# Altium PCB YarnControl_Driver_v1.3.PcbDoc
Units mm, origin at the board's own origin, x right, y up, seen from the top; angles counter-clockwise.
Board outline 80 x 60 mm, 2 copper layers (Top Layer, Bottom Layer); 141 components, 102 nets, 453 pads, 202 vias.
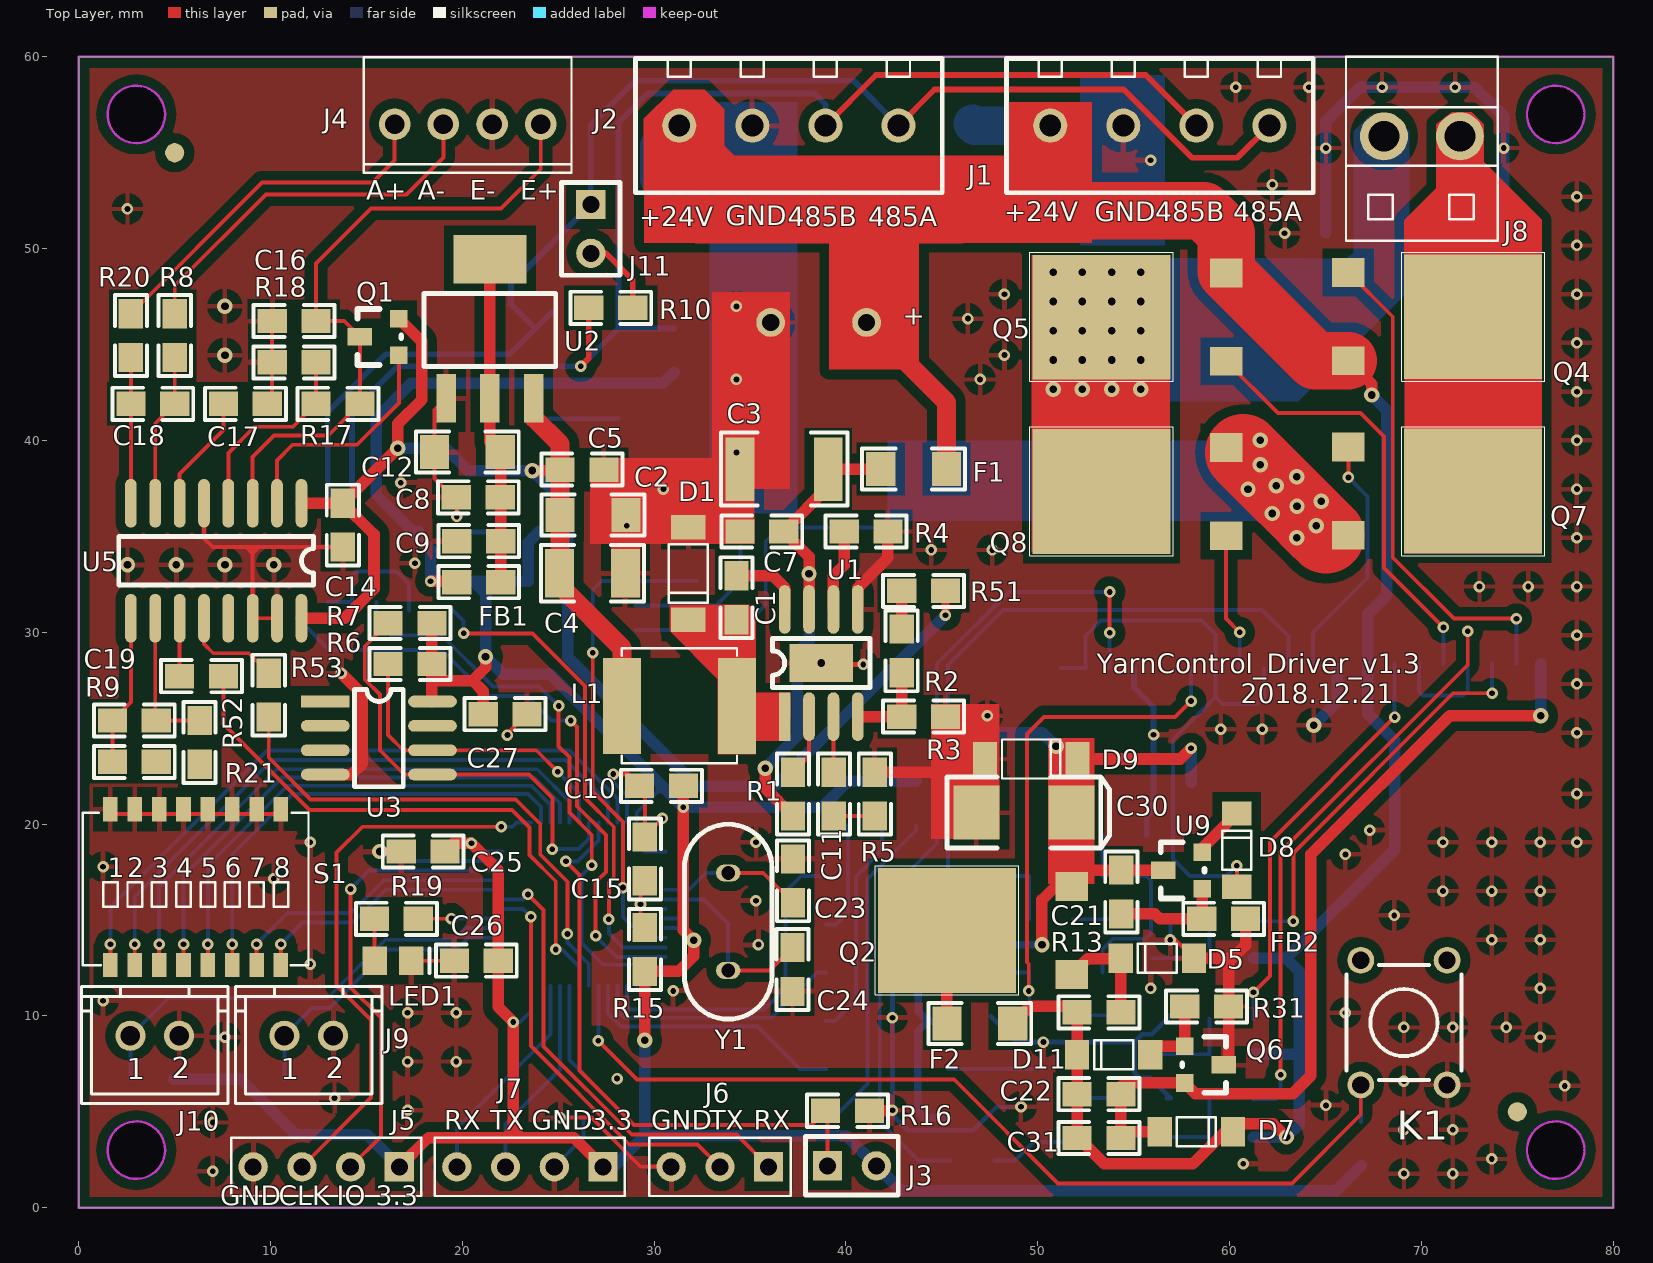
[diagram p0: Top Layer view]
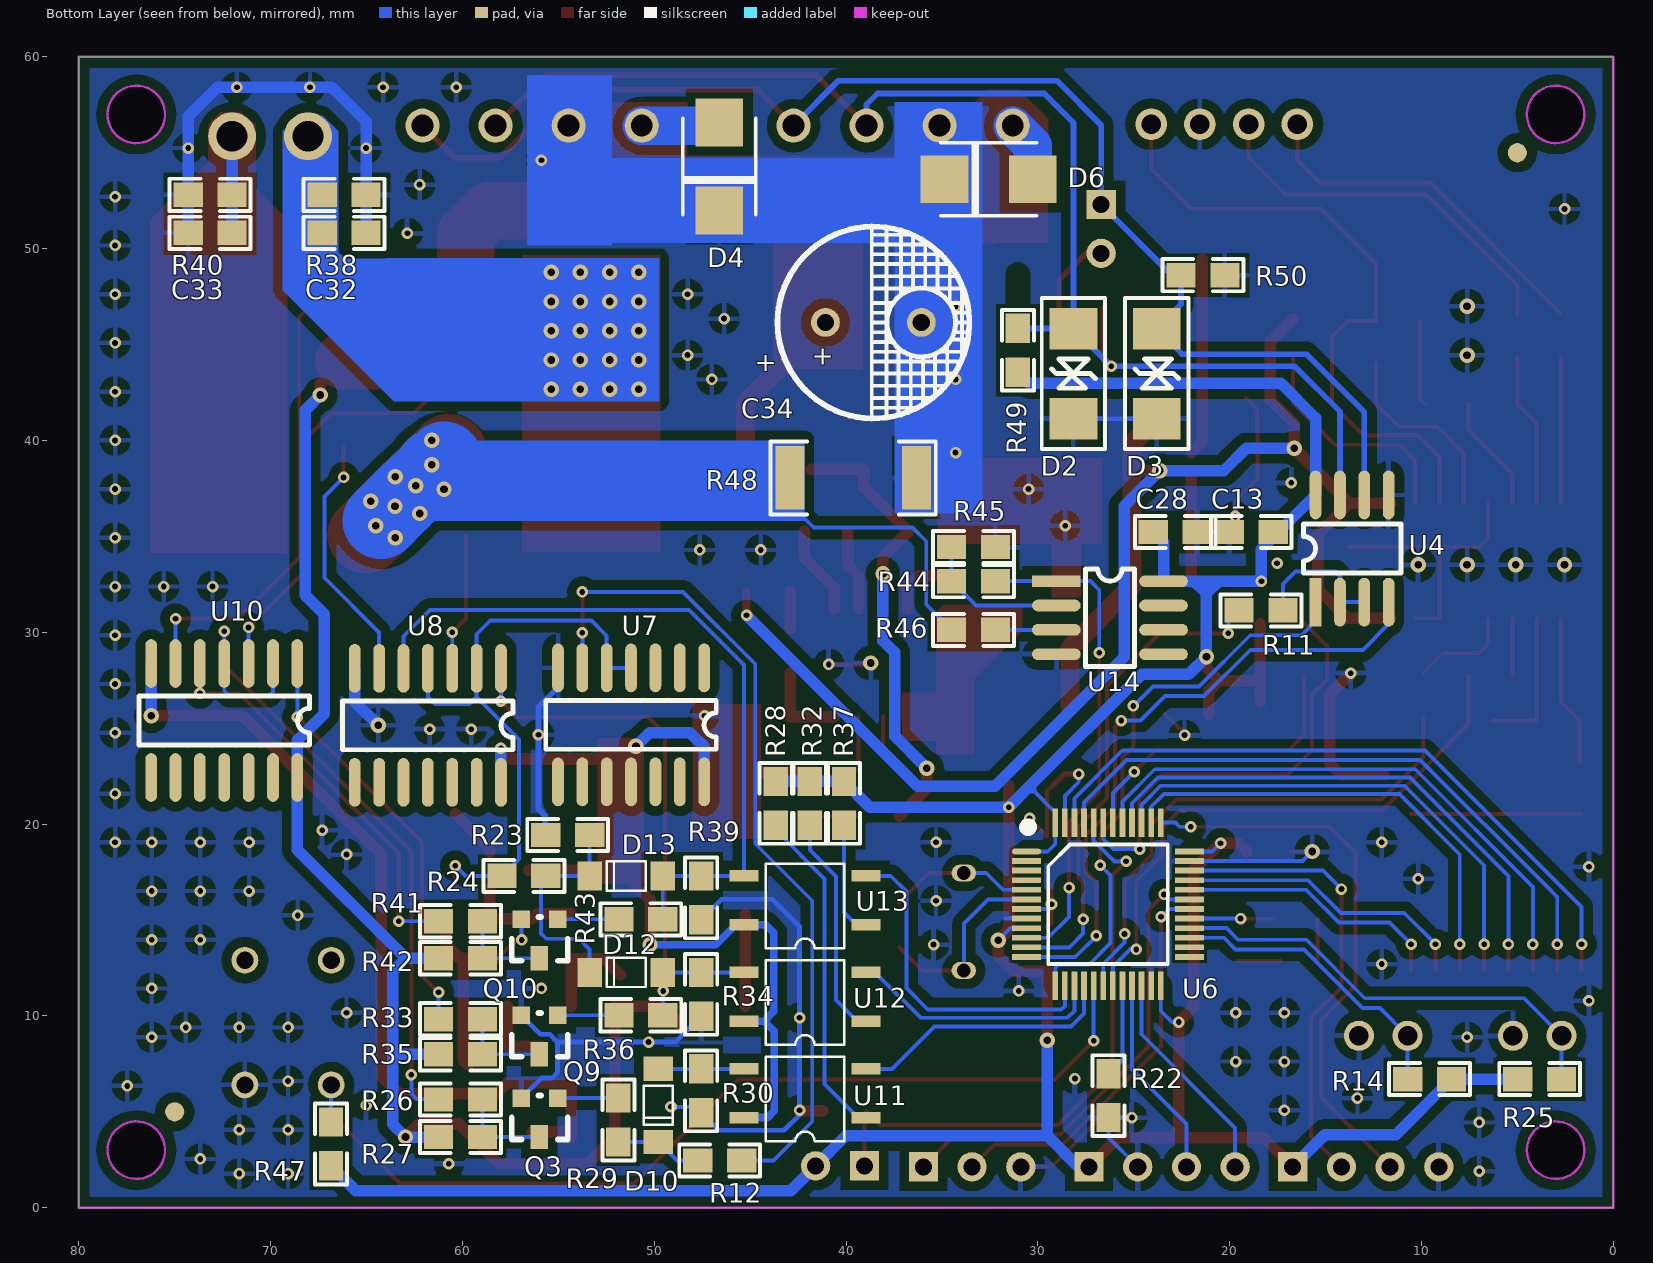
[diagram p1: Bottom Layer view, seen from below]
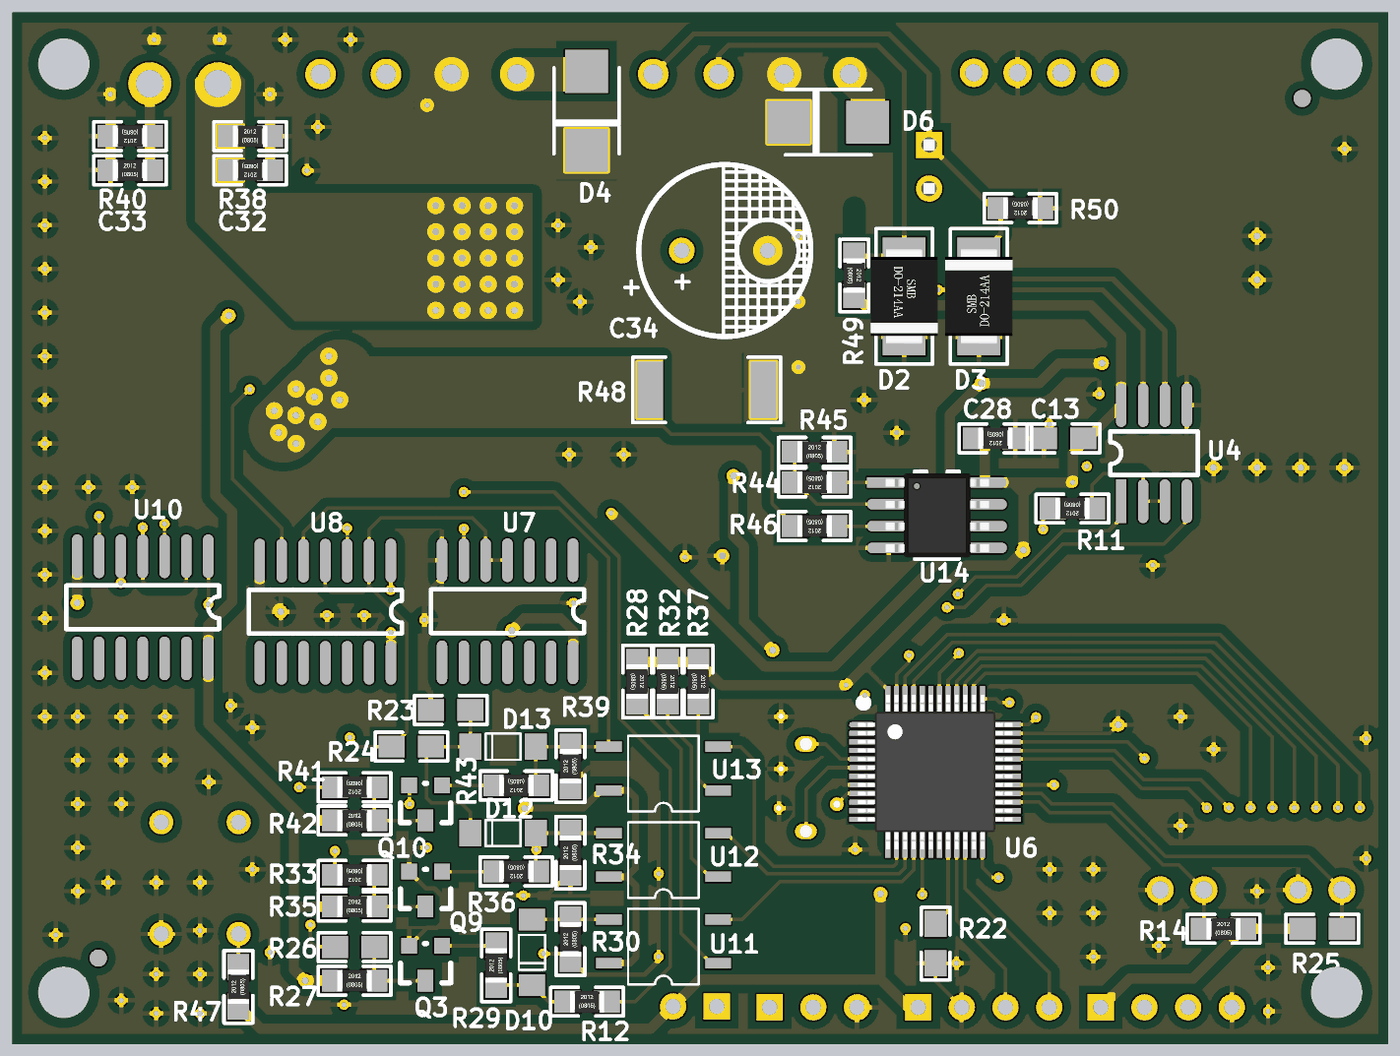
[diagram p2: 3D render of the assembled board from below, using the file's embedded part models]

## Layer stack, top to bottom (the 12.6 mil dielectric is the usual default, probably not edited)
Top Layer: signal copper 0.0356
Dielectric: dielectric 0.32, FR-4, Dk 4.8
Bottom Layer: signal copper 0.0356

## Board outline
0,0 80,0 80,60 0,60
cut-out: 3,1.5 cw(c3,3) 1.5,3 cw(c3,3) 3,4.5 cw(c3,3) 4.5,3 cw(c3,3)
cut-out: 75.5,3 ccw(c77,3) 77,1.5 ccw(c77,3) 78.5,3 ccw(c77,3) 77,4.5 ccw(c77,3)
cut-out: 75.5,57 ccw(c77,57) 77,55.5 ccw(c77,57) 78.5,57 ccw(c77,57) 77,58.5 ccw(c77,57)
cut-out: 3,55.5 cw(c3,57) 1.5,57 cw(c3,57) 3,58.5 cw(c3,57) 4.5,57 cw(c3,57)

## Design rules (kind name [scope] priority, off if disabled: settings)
Clearance LQFP_48 [(HasFootprint('LQFP_48'))] p1: gap=0.178
Clearance poly [inpoly] p2: gap=0.508
Clearance [All] p3: gap=0.203
Height [All] p1: minheight=0 maxheight=50 prefheight=12.7
HoleSize [All] p1: absolutevalues=TRUE maxlimit=4 minlimit=0.025 maxpercent=80.000 minpercent=20.000
MinimumSolderMaskSliver [All] p1: minsoldermaskwidth=0
PolygonConnect [All] p1: connectstyle=Relief reliefconductorwidth=0.254 reliefentries=4 polygonreliefangle="90 Angle"
RoutingVias [All] p1: holewidth=0.711 width=1.27 viastyle="Through Hole" minholewidth=0.3 minwidth=0.6 maxholewidth=0.711 maxwidth=1.27
SilkToSilkClearance [All] p1: silktosilkclearance=0
SilkscreenOverComponentPads [All] p1: minsilkscreentomaskgap=0
SolderMaskExpansion [All] p1: expansion=0.102
Width [All] p1: maxlimit=5 minlimit=0.203 preferedwidth=0.203
23 further rules are at their usual default settings.

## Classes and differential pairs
component class YarnControl_Driver_v1.3: C1 C2 C3 C4 C5 C7 C8 C9 C10 C11 C12 C13 C14 C15 C16 C17 C18 C19 C23 C24 C25 C26 C27 C28 D1 D2 D3 F1 FB1 J1 J2 J3 J4 J5 J6 J7 J9 J10 J11 K1 L1 LED1 Q1 R1 R2 R3 R4 R5 R6 R7 R8 R9 R10 R11 R14 R15 R16 R17 R18 R19 R20 R21 R22 R25 R47 R49 R50 R51 R52 R53 R? S1 U1 U2 U3 U4 U5 U6 Y1
component class YarnControl_motor_v1.3: C21 C22 C30 C31 C32 C33 C34 D4 D5 D6 D7 D8 D9 D10 D11 D12 D13 F2 FB2 J8 Q2 Q3 Q4 Q5 Q6 Q7 Q8 Q9 Q10 R12 R13 R23 R24 R26 R27 R28 R29 R30 R31 R32 R33 R34 R35 R36 R37 R38 R39 R40 R41 R42 R43 R44 R45 R46 R48 U7 U8 U9 U10 U11 U12 U13 U14

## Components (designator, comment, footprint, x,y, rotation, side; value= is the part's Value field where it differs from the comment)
C1 "0.1uF" 0805#1 34.29,32.944 r270 top
C2 "22uF" 1206 28.524,36.119 r180 top
C3 "47uF" 1812 36.779,38.506 r180 top
C4 "47uF" 1210 28.499,33.071 r180 top
C5 "0.1uF" 0805#1 27.381,38.481 r180 top
C7 "0.1uF" 0805#1 36.754,35.255 r180 top
C8 "10uF" 0805#1 19.685,37.033 r0 top
C9 "0.1uF" 0805#1 19.71,34.747 r0 top
C10 "0.1uF" 0805#2 30.378,21.996 r180 top
C11 "150pF" 0805#1 39.37,22.708 r270 top
C12 "22uF" 1206 21.971,39.395 r180 top
C13 "0.1uF" 0805#1 20.015,35.23 r180 bottom
C14 "1uF" 0805#1 13.767,34.442 r90 top
C15 "0.1uF" 0805#1 29.515,19.329 r270 top
C16 "1uF" 0805#1 10.084,46.228 r0 top
C17 "1uF" 0805#1 7.544,41.91 r0 top
C18 "0.1uF" 0805#1 5.004,41.91 r180 top
C19 "0.1uF" 0805#1 1.753,25.4 r0 top
C21 "10uF" 0805#1 54.356,17.602 r270 top
C22 "10nF" 0805#1 52.045,5.918 r0 top
C23 "22pF" 0805#2 37.236,17.043 r270 top
C24 "22pF" 0805#2 37.211,12.421 r90 top
C25 "0.1uF" 0805#2 17.958,18.567 r0 top
C26 "0.1uF" 0805#2 20.726,12.878 r0 top
C27 "0.1uF" 0805#2 22.225,25.73 r180 top
C28 "0.1uF" 0805#2 22.835,35.23 r0 bottom
C30 "100uF" CA6032-C 49.276,20.599 r0 top
C31 "22uF" 0805#2 53.188,3.632 r180 top
C32 "10nF" 0805#2 66.167,50.825 r0 bottom
C33 "10nF" 0805#2 73.152,50.825 r180 bottom
C34 "1000uF/35V" CAP-5MM 41.072,46.152 r180 bottom
D1 "1N5819" Diode_TP2 31.775,35.484 r270 top
D2 "SMBJ6.5CA" SMBJ_DO-214 28.143,43.485 r270 bottom
D3 "SMBJ6.5CA" SMBJ_DO-214 23.8,43.485 r90 bottom
D4 "SMCJ24A" DO-214AA/SMB 46.609,54.28 r270 bottom
D5 "ZMM6V2" DIDODE_LL-34 56.236,13.005 r180 top
D6 "SMCJ24A" DO-214AA/SMB 32.563,53.619 r0 bottom
D7 "ZMM6V2" DIDODE_LL-34 58.268,3.962 r0 top
D8 "1N4148" DIDODE_LL-34 60.376,18.644 r90 top
D9 "SMAJ5.0A" Diode_TP2 47.244,23.393 r0 top
D10 "1N4148" DIDODE_LL-34 49.784,5.334 r270 bottom
D11 "ZMM6V2" DIDODE_LL-34 53.95,7.976 r180 top
D12 "1N4148" DIDODE_LL-34 51.46,12.268 r0 bottom
D13 "1N4148" DIDODE_LL-34 51.46,17.297 r0 bottom
F1 "FUSE" 1206 45.237,38.506 r180 top
F2 "FUSE" 1206 45.263,9.601 r0 top
FB1 "FERRITE" 0805#1 21.996,32.614 r180 top
FB2 "FERRITE" 0805#2 59.69,15.062 r0 top
J1 "SH-4" J381-180 56.363,56.413 r180 top
J2 "SH-4" J381-180 37.02,56.413 r180 top
J3 "Jumper" J254-2 39.04,2.184 r0 top
J4 "SH-4" KF2510-4 24.088,56.49 r180 top
J5 "SH-4" J254-4 16.713,2.134 r180 top
J6 "SH-3" J2.54-3 33.426,2.134 r180 top
J7 "SH-4" J254-4 27.33,2.134 r180 top
J8 "SH-2" CH3.96-2P 70.028,55.855 r0 top
J9 "SWITCH1" XH2.54-2T 10.719,8.966 r0 top
J10 "SWITCH2" XH2.54-2T 2.692,8.966 r0 top
J11 "Jumper" J254-2 26.695,52.299 r270 top
K1 "BUTTON_4" Button1 69.088,9.652 r90 top
L1 "4.7uH" Inductance6*6 31.318,26.162 r180 top
LED1 "GREEN" LED 16.383,12.878 r0 top
Q1 "S8550" 901X_SOT-23 14.656,45.415 r90 top
Q2 "2SD1760" TO-252-2L 48.514,14.453 r90 top
Q3 "MMBT3904" SOT-23 55.982,3.683 r0 bottom
Q4 "NCE40P70K" TO-252 72.695,46.457 r270 top
Q5 "NCE40P70K" TO-252 53.315,46.431 r90 top
Q6 "MMBT2907A" 901X_SOT-23 59.69,7.442 r270 top
Q7 "NCE6075" TO-252 72.695,37.363 r270 top
Q8 "NCE6075" TO-252 53.315,37.338 r90 top
Q9 "MMBT3904" SOT-23 55.982,8.001 r0 bottom
Q10 "MMBT3904" SOT-23 55.982,13.005 r0 bottom
R1 "100K" 0805#1 37.236,22.708 r270 top
R2 "200K" 0805#1 42.901,30.175 r270 top
R3 "40.2K" 0805#1 45.187,25.603 r180 top
R4 "100K" 0805#1 42.189,35.255 r180 top
R5 "100K" 0805#1 41.504,22.708 r270 top
R6 "10K" 0805#1 16.129,28.346 r0 top
R7 "10K" 0805#1 16.129,30.48 r0 top
R8 "1K" 0805#2 5.004,45.466 r90 top
R9 "1K" 0805#2 2.896,23.241 r0 top
R10 "120R" 0805#1 26.594,46.914 r0 top
R11 "1K" 0805#2 18.364,31.14 r0 bottom
R12 "4.7K" 0805#2 46.584,2.464 r180 bottom
R13 "5.6K" 0805#2 53.188,10.185 r0 top
R14 "10K" 0805#2 9.576,6.706 r180 bottom
R15 "10K" 0805#1 29.515,14.605 r270 top
R16 "10K" 0805#1 38.938,5.055 r0 top
R17 "20K" 0805#1 12.37,41.91 r0 top
R18 "8.2K" 0805#1 12.37,44.069 r180 top
R19 "1K" 0805#1 15.418,15.062 r0 top
R20 "1K" 0805#1 2.718,44.323 r90 top
R21 "1K" 0805#1 6.299,25.4 r270 top
R22 "10K" 0805#1 26.314,4.699 r90 bottom
R23 "10K" 0805#1 55.651,19.431 r180 bottom
R24 "10K" 0805#1 55.651,17.297 r0 bottom
R25 "10K" 0805#1 4.978,6.706 r180 bottom
R26 "10K" 0805#1 58.953,5.639 r0 bottom
R27 "10K" 0805#2 60.096,3.683 r180 bottom
R28 "510R" 0805#2 43.663,21.082 r270 bottom
R29 "10K" 0805#2 51.867,4.572 r90 bottom
R30 "510R" 0805#2 47.549,6.096 r90 bottom
R31 "5.6K" 0805#2 58.801,10.49 r180 top
R32 "510R" 0805#2 41.885,21.082 r270 bottom
R33 "10K" 0805#2 60.096,9.83 r0 bottom
R34 "4.7K" 0805#2 47.549,11.125 r90 bottom
R35 "10K" 0805#2 60.096,8.001 r180 bottom
R36 "10K" 0805#2 50.698,10.033 r0 bottom
R37 "510R" 0805#2 40.107,21.082 r270 bottom
R38 "1M" 0805#2 66.167,52.807 r180 bottom
R39 "4.7K" 0805#2 47.549,16.154 r90 bottom
R40 "1M" 0805#2 73.152,52.807 r0 bottom
R41 "10K" 0805#2 60.096,14.935 r0 bottom
R42 "10K" 0805#2 60.096,13.005 r180 bottom
R43 "10K" 0805#2 50.698,15.037 r0 bottom
R44 "10K" 0805#2 33.35,32.664 r0 bottom
R45 "1K" 0805#2 33.35,34.442 r180 bottom
R46 "1K" 0805#2 33.35,30.124 r0 bottom
R47 "10K" 0805#2 66.853,3.327 r90 bottom
R48 "R100" 2512 39.624,38.049 r0 bottom
R49 "360R" 0805#2 31.039,44.704 r270 bottom
R50 "360R" 0805#2 21.387,48.616 r0 bottom
R51 "10K" 0805#2 44.044,32.156 r180 top
R52 "1K" 0805#1 7.544,27.711 r180 top
R53 "1K" 0805#1 9.906,25.578 r90 top
S1 "SW-CH8" SWITCH_8 6.096,16.713 r0 top
U1 "MP1584" MP1584 38.71,28.397 r90 top
U2 "AMS1117" TO-223 21.438,45.822 r0 top
U3 "SMEC98SP" SO-8#1 15.646,24.486 r0 top
U4 "SP3485" SO-8#1 13.614,34.366 r90 bottom
U5 "HX711" SO-16 11.608,36.728 r270 top
U6 "STM32F103C8T6" LQFP_48 26.34,15.824 r180 bottom
U7 "74VHC00" SO-14 47.396,28.143 r270 bottom
U8 "74VHC08" SO-14 57.988,28.118 r270 bottom
U9 "MAX809" SOT-23 56.54,17.602 r90 top
U10 "74VHC00" SO-14 68.605,28.372 r270 bottom
U11 "EL357N" EL357N 42.139,5.969 r0 bottom
U12 "EL357N" EL357N 42.139,10.998 r0 bottom
U13 "EL357N" EL357N 42.139,16.027 r0 bottom
U14 "LM358" SO-8#2 29.032,32.664 r180 bottom
Y1 "8M" XTAL 33.858,12.37 r90 top

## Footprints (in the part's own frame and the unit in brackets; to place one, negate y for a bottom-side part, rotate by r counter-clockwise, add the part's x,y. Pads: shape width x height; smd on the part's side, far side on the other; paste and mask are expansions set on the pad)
0805#1 [mil]
  rect 60x50 smd: 1(0,0) 2(90,0)
  silkscreen extent -38,-33 128,33
0805#2 [mil]
  rect 60x50 smd: 1(-45,0) 2(45,0)
  silkscreen extent -83,-33 83,33, body extent -39,-25 39,24, height 18
901X_SOT-23 [mil]
  rect 36x50 smd: 1(0,0)
  rect 36x36 smd: 2(-38,-80) 3(37,-80)
  silkscreen extent -58,-85 57,5
1206 [mil]
  rect 60x70 smd: 1(0,0) 2(135,0)
  silkscreen extent -38,-42 173,42
1210 [mil]
  rect 60x100 smd: 1(0,0) 2(135,0)
  silkscreen extent -38,-58 173,58
1812 [mm]
  rect 1.5x3.3 smd: 1(-2.3,0) 2(2.3,0)
  silkscreen extent -3.3,-1.91 3.3,1.91
2512 [mm]
  rect 1.5x3.3 smd: 1(-3.3,0) 2(3.3,0)
  silkscreen extent -4.3,-1.91 4.3,1.91
Button1 [mm]
  round 1.4 hole 0.9: 1(-3.25,2.25) 2(3.25,2.25) 3(-3.25,-2.25) 4(3.25,-2.25)
  silkscreen extent -3,-3 3,3, body extent -3.94,-3 4.03,3, height 4.9
CA6032-C [mm]
  rect 2.4x2.8 smd: 1(2.48,0) 2(-2.48,0)
  silkscreen extent -4.01,-1.85 4.47,1.85, body extent -3.05,-1.68 3.05,1.67, height 2.7
CAP-5MM [mm]
  round 1.5 hole 0.9: 1(0,0) 2(5,0)
  silkscreen extent -2.5,-5 7.5,5
CH3.96-2P [mm]
  round 2.5 hole 1.6: 1(-1.98,0) 2(1.98,0)
  silkscreen extent -3.96,-5.45 3.96,4.15
DIDODE_LL-34 [mil]
  rect 50x60 smd: 1(-75,0) 2(75,0)
  silkscreen extent -40,-30 40,30
Diode_TP2 [mil]
  rect 50x70 smd: 1(0,0) 2(190,0)
  silkscreen extent 35,-40 155,40
DO-214AA/SMB [mm]
  rect 2.5x2.5 smd: 1(-2.3,0) 2(2.3,0)
  silkscreen extent -2.5,-1.9 2.5,1.9
EL357N [mm]
  rect 1.5x0.6 smd: 1(-3.175,1.27) 2(-3.175,-1.27) 3(3.175,-1.27) 4(3.175,1.27)
  silkscreen extent -2.05,-1.9 2.05,2.5
Inductance6*6 [mm]
  rect 2x5 smd: 1(-3,0) 2(3,0)
  silkscreen extent -3,-3 3,3
J2.54-3 [mil]
  rect 60x60 hole 35: 1(-100,0)
  round 60 hole 35: 2(0,0) 3(100,0)
  silkscreen extent -145,-60 145,60
J254-2 [mil]
  rect 60x60 hole 35: 1(0,0)
  round 60 hole 35: 2(100,0)
  silkscreen extent -45,-60 145,60
J254-4 [mil]
  rect 60x60 hole 35: 1(0,0)
  round 60 hole 35: 2(100,0) 3(200,0) 4(300,0)
  silkscreen extent -45,-60 345,60
J381-180 [mil]
  round 70 hole 45: 1(-225,0) 2(-75,0) 3(75,0) 4(225,0)
  silkscreen extent -315,-138 315,138
KF2510-4 [mil]
  round 65 hole 40: 1(0,0) 2(100,0) 3(200,0) 4(300,0)
  silkscreen extent -63,-138 363,100
LED [mm]
  rect 1.3x1.5 smd: 1(-0.95,0) 2(0.95,0)
  silkscreen extent 1.9,-0.65 1.9,0.65
LQFP_48 [mm]
  oval 1.5x0.3 smd: 1(-4.25,2.75)
  rect 1.5x0.3 smd: 2(-4.25,2.25) 3(-4.25,1.75) 4(-4.25,1.25) 5(-4.25,0.75) 6(-4.25,0.25) 7(-4.25,-0.25) 8(-4.25,-0.75) 9(-4.25,-1.25) 10(-4.25,-1.75) 11(-4.25,-2.25) 12(-4.25,-2.75) 25(4.25,-2.75) 26(4.25,-2.25) 27(4.25,-1.75) 28(4.25,-1.25) 29(4.25,-0.75) 30(4.25,-0.25) 31(4.25,0.25) 32(4.25,0.75) 33(4.25,1.25) 34(4.25,1.75) 35(4.25,2.25) 36(4.25,2.75)
  rect 0.3x1.5 smd: 13(-2.75,-4.25) 14(-2.25,-4.25) 15(-1.75,-4.25) 16(-1.25,-4.25) 17(-0.75,-4.25) 18(-0.25,-4.25) 19(0.25,-4.25) 20(0.75,-4.25) 21(1.25,-4.25) 22(1.75,-4.25) 23(2.25,-4.25) 24(2.75,-4.25) 37(2.75,4.25) 38(2.25,4.25) 39(1.75,4.25) 40(1.25,4.25) 41(0.75,4.25) 42(0.25,4.25) 43(-0.25,4.25) 44(-0.75,4.25) 45(-1.25,4.25) 46(-1.75,4.25) 47(-2.25,4.25) 48(-2.75,4.25)
  silkscreen extent -4.33,-3.11 3.11,4.18, body extent -4.5,-4.5 4.5,4.5, height 1.6
MP1584 [mil]
  rect 78.74x129.92 smd: 0(0,0)
  rect 100x24 smd: 1(-110,75)
  oval 100x24 smd: 2(-110,25) 3(-110,-25) 4(-110,-75) 5(110,-75) 6(110,-25) 7(110,25) 8(110,75)
  silkscreen extent -50,-100 50,100
SMBJ_DO-214 [mm]
  rect 2.16x2.5 smd: 1(-2.35,0) 2(2.35,0)
  silkscreen extent -3.94,-1.65 3.94,1.65, body extent -2.8,-1.95 2.8,1.95, height 2.5
SO-8#1 [mil]
  rect 100x24 smd: 1(-110,75)
  oval 100x24 smd: 2(-110,25) 3(-110,-25) 4(-110,-75) 5(110,-75) 6(110,-25) 7(110,25) 8(110,75)
  silkscreen extent -50,-100 50,100
SO-8#2 [mil]
  rect 100x24 smd: 1(0,0)
  oval 100x24 smd: 2(0,-50) 3(0,-100) 4(0,-150) 5(220,-150) 6(220,-100) 7(220,-50) 8(220,0)
  silkscreen extent 60,-175 160,25, body extent -7,-172 229,21, height 67
SO-14 [mil]
  oval 100x24 smd: 1(0,0) 2(0,-50) 3(0,-100) 4(0,-150) 5(0,-200) 6(0,-250) 7(0,-300) 8(234,-300) 9(234,-250) 10(234,-200) 11(234,-150) 12(234,-100) 13(234,-50) 14(234,0)
  silkscreen extent 67,-325 167,25
SO-16 [mil]
  oval 100x24 smd: 1(0,0) 2(0,-50) 3(0,-100) 4(0,-150) 5(0,-200) 6(0,-250) 7(0,-300) 8(0,-350) 9(236,-350) 10(236,-300) 11(236,-250) 12(236,-200) 13(236,-150) 14(236,-100) 15(236,-50) 16(236,0)
  silkscreen extent 68,-375 168,25
SOT-23 [mil]
  rect 36x36 smd: 1(-38,-80) 2(37,-80)
  rect 36x50 smd: 3(0,0)
  silkscreen extent -58,-85 57,5
SWITCH_8 [mm]
  rect 0.76x1.27 smd: 1(-4.445,-4.06) 2(-3.175,-4.06) 3(-1.905,-4.06) 4(-0.635,-4.06) 5(0.635,-4.06) 6(1.905,-4.06) 7(3.175,-4.06) 8(4.445,-4.06) 9(4.445,4.06) 10(3.175,4.06) 11(1.905,4.06) 12(0.635,4.06) 13(-0.635,4.06) 14(-1.905,4.06) 15(-3.175,4.06) 16(-4.445,4.06)
  silkscreen extent -5.88,-4.06 5.88,3.88
TO-223 [mil]
  rect 150x100 smd: 0(0,142.5)
  rect 40x100 smd: 1(-90,-142.5) 2(0,-142.5) 3(90,-142.5)
  silkscreen extent -135,-78 135,72
TO-252 [mm]
  rect 6.5x7.2 smd: 1(0,0)
  rect 1.5x1.7 smd: 2(-2.3,-6.5) 3(2.3,-6.5)
  silkscreen extent -3.35,-3.73 3.38,3.73
TO-252-2L [mm]
  rect 1.5x1.7 smd: 1(-2.3,-3.25) 3(2.3,-3.25)
  rect 6.5x7.2 smd: 2(0,3.25)
  silkscreen extent -3.35,-0.48 3.38,6.98
XH2.54-2T [mil]
  round 62 hole 40: 1(0,0) 2(100,0)
  silkscreen extent -100,-139 200,101
XTAL [mil]
  oval 35x50 hole 28: 1(0,0) 2(200,0)
  silkscreen extent -100,-90 300,90, body extent -121,-93 319,91, height 143

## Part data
C1 C2 C3 C7 C11 C12 C14 C16 C17 C18 C19 C21 C22 C23 C24 C31 C32 C33: library part CAP, "电容"
C4 C5 C8 C9: library part Cap0805
C10 C13 C15 C25 C26 C27 C28: library part Cap, "Capacitor"
C30: library part CapAEC*4
C34: library part "Cap Pol1", "Polarized Capacitor (Radial)"
D1: library part Diode, "二极管"
D2 D3 D4 D6 D9: library part TVS
D5 D7 D11: library part "D Zener", "Zener Diode"
D8 D10 D12 D13: library part Diode, "Default Diode"
F1 F2: "保险丝"
J9 J10: library part SH-2
L1: library part Inductor, "电感"
LED1: library part LED2, "Typical RED, GREEN, YELLOW, AMBER GaAs LED"
Q1 Q6: library part PNP
Q3 Q9 Q10: library part S8050
Q4 Q5: library part MOSFET-P, "P-Channel MOSFET"
Q7 Q8: library part MOSFET-N, "N-Channel MOSFET"
R1 R2 R3 R4 R5 R8 R9 R12 R13 R16 R17 R18 R19 R20 R21 R23 R24 R26 R27 R28 R29 R30 R31 R32 R33 R34 R35 R36 R37 R38 R39 R40 R41 R42 R43 R44 R45 R46 R48 R51 R52 R53: library part RES, "电阻"
R6 R7 R10 R11 R14 R15 R22 R25 R47 R49 R50: library part Res2, "Resistor"
S1: "拨码开关CH8"
U4: "485"
U8: library part 74HC08
U11 U12 U13: library part TLP521
Y1: library part XTAL, "Crystal Oscillator"

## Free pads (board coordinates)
  round 1 smd: 0(5,55) 0(75,5)
  round 1 smd far side: 0(5,55) 0(75,5)

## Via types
v1: diameter 0.6, hole 0.3, Top Layer to Bottom Layer, 151 vias
v2: diameter 0.8, hole 0.4, Top Layer to Bottom Layer, 51 vias

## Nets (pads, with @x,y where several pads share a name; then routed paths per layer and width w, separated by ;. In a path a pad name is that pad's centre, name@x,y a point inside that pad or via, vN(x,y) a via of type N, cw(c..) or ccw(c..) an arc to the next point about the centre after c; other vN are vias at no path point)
485_DE: R11.2 U6.11 | length 25.8
  Top Layer w0.203: v1(20.066,29.947) 23.647,29.947 26.391,27.203 26.391,21.361 27.889,19.863 27.889,17.221 27.635,16.967 v1(27.635,15.037)
  Bottom Layer w0.203: R11.2 20.066,30.582 v1(20.066,29.947) ; v1(27.635,15.037) 27.635,14.3 28.361,13.574 U6.11
485_RX: U4.1 U6.13 | length 30
  Top Layer w0.203: v1(25.019,26.162) 25.019,24.054 25.578,23.495 25.578,20.599 26.746,19.431 v1(26.746,17.856)
  Bottom Layer w0.203: U4.1 15.519,30.582 16.256,29.845 18.923,29.845 21.59,27.178 24.003,27.178 v1(25.019,26.162) ; v1(26.746,17.856) 26.213,17.323 26.213,13.792 27.337,12.668 28.912,12.668 29.09,12.49 U6.13
485_TX: U4.4 U6.12 | length 33.5
  Top Layer w0.203: v1(25.654,25.4) 25.984,25.07 25.984,20.93 27.483,19.431 27.483,17.501 26.949,16.967 v1(26.949,14.173)
  Bottom Layer w0.203: U4.4 11.709,30.429 13.056,29.083 18.923,29.083 21.336,26.67 23.368,26.67 24.638,25.4 v1(25.654,25.4) ; v1(26.949,14.173) 28.048,13.074 U6.12
+3.3V: C10.1 C13.2 C25.2 C26.2 C27.2 C28.2 FB1.2 J3.2 J5.1 J7.1 R6.2 R7.2 R14.2 R15.2 R25.1 R28.1 R32.1 R37.1 R47.1 R49.2 U3.8 U4.8 U6.1 U6.9 U6.24 U6.36 U6.48 U14.8 | length 196.2
  Top Layer w0.203: C27.2 C27.2@21.26,25.73
  Top Layer w0.6: J5.1 18.237,3.658 22.276,3.658 ; v1(18.339,32.664) FB1.2@19.66,32.664 ; U3.8@18.415,26.391 18.415,27.432 ; R7.2@18.415,29.947 18.415,29.616 ; R7.2@18.415,30.455 18.415,29.616 ; C25.2 19.533,18.999 v1(20.472,18.999) 21.869,17.602 21.869,10.465 v1(22.657,9.677) 22.657,4.039 ; C27.2@21.057,25.756 C27.2 21.082,26.924 20.523,27.483 ; v2(21.209,28.727) 21.209,28.169 20.523,27.483 ; J7.1 25.806,3.658 23.038,3.658 ; v2(29.515,8.738) R15.2 31.267,12.319 32.055,13.106 v2(32.055,13.945) 31.521,14.478 v1(31.521,20.879) C10.1 ; 18.415,27.432 18.466,27.483 20.523,27.483 ; 18.415,27.432 R6.2 18.415,29.616 ; 22.276,3.658 22.657,4.039 ; 22.276,3.658 23.038,3.658 ; 22.657,4.039 23.038,3.658
  Bottom Layer w0.203: v1(20.472,18.999) 20.904,18.567 U6.36@22.083,18.567 ; 23.012,9.677 23.59,10.255 U6.24 ; 30.175,22.186 30.175,21.692 ; 30.455,21.971 30.442,21.958 30.175,21.692 ; U6.9 31.425,14.574 v2(32.055,13.945) ; U6.1 29.483,18.574 29.09,18.967 U6.48 29.09,20.606 30.175,21.692 ; 30.658,21.692 30.175,21.692
  Bottom Layer w0.6: R25.1@4.953,6.706 R25.1 R14.2@8.357,6.706 ; R14.2 11.328,3.81 15.037,3.81 J5.1 ; C13.2 C13.2@17.45,35.23 ; C28.2 23.444,34.696 U14.8 21.844,32.664 ; J7.1 27.889,2.134 29.515,3.759 ; v2(29.515,8.738) 29.515,3.759 ; R49.2 30.455,42.977 17.323,42.977 15.519,41.173 U4.8 C13.2@17.45,35.23 ; R28.1 R32.1 R37.1 38.76,20.879 v1(31.521,20.879) 30.442,21.958 24.587,27.813 22.123,27.813 v2(21.209,28.727) 21.209,32.029 ; R47.1 65.557,0.889 42.875,0.889 J3.2 40.005,3.759 29.515,3.759 ; C13.2@17.45,35.23 18.339,34.341 v1(18.339,32.664) 20.574,32.664 ; 20.574,32.664 21.209,32.664 ; 20.574,32.664 21.209,32.029 ; 21.209,32.029 21.209,32.664 ; 21.209,32.029 21.844,32.664 ; 21.209,32.664 21.844,32.664
+5V: C2.2 C4.2 C5.2 C14.2 L1.2 Q1.3 R51.1 U2.3 U5.1 U5.16 | length 87.7
  Top Layer w0.4: C5.2@24.765,38.481 C5.2 ; L1.2 L1.2@28.321,26.165 ; v1(45.187,30.886) R51.1
  Top Layer w0.6: U5.16 13.868,30.734 15.392,32.258 15.392,35.103 C14.2 ; U5.1 C14.2 ; Q1.3 17.882,45.161 17.882,42.113 16.637,40.869 v2(16.637,39.599) C14.2 ; v2(23.647,38.43) 25.044,38.43 C5.2
  Top Layer w1: U2.3@23.724,41.186 25.095,39.814 C5.2 25.095,32.408 28.318,29.185 L1.2
  Bottom Layer w0.6: v2(16.637,39.599) 19.126,39.599 20.295,38.43 v2(23.647,38.43) 25.502,36.576 25.502,28.702 32.233,21.971 36.271,21.971 v1(45.187,30.886)
+24V: C22.1 C31.2 C34.1 D4.1 D6.1 D7.2 D11.2 F1.1 F2.2 J1.4 J2.4 Q4.3 Q5.3 R13.1 R27.1 R35.1 R42.1 U10.14 | length 114.5
  Top Layer w0.6: F2.2 49.581,10.49 52.045,10.49 R13.1 D11.2 C22.1 52.045,3.708 52.083,3.67 53.467,2.286 58.09,2.286 59.969,4.166 60.173,4.369 62.281,4.369 v2(62.967,3.683) ; Q4.3 67.412,42.94 v2(67.412,42.367)
  Top Layer w1: C34.1 45.237,41.986 F1.1
  Top Layer w3: 47.015,51.968 58.649,51.968 59.815,50.802 59.815,48.796 59.847,48.764 64.454,44.157 Q4.3
  Bottom Layer w0.6: R27.1 v2(62.967,3.683) 63.627,4.343 63.627,7.976 ; R35.1 63.602,8.001 63.627,7.976 ; R42.1 62.941,13.005 ; v2(67.412,42.367) 68.199,41.58 68.199,31.928 67.208,30.937 67.208,25.756 68.605,24.359 U10.14 68.605,18.669 62.941,13.005 ; 62.941,13.005 63.627,12.319 63.627,7.976
  Bottom Layer w2: D6.1 30.263,55.371 J2.4 ; D4.1@46.609,56.515 46.711,56.413 J1.4
BOOT0: J3.1 R16.1 U6.44 | length 31.5
  Top Layer w0.203: v1(25.4,18.059) 26.111,17.348 26.111,7.163 28.956,4.318 38.202,4.318 R16.1 39.04,4.953 J3.1
  Bottom Layer w0.203: v1(25.4,18.059) 26.01,18.059 27.09,19.14 U6.44
BOOT1: R22.2 U6.20 | length 4.9
  Bottom Layer w0.203: U6.20 25.59,7.71 R22.2
BT_RXD: J7.4 U6.22 | length 11.5
  Bottom Layer w0.203: J7.4 19.71,4.166 24.59,9.045 U6.22
BT_TXD: J7.3 U6.21 | length 10.6
  Bottom Layer w0.203: J7.3 22.25,4.369 25.09,7.208 U6.21
CLEAR: K1.1 R47.2 U6.17 | length 50.6
  Top Layer w0.203: v1(27.09,8.699) 29.108,6.68 45.644,6.68 51.054,1.27 63.246,1.27 66.838,4.862 K1.1
  Bottom Layer w0.203: v1(27.09,8.699) U6.17 ; R47.2 K1.1@66.853,6.387
ENA: U6.16 U11.2 | length 14
  Bottom Layer w0.203: U6.16 27.59,10.129 28.27,9.449 35.382,9.449 37.592,7.239 U11.2
GND: C2.1 C3.2 C4.1 C5.1 C7.2 C8.1 C9.1 C10.2 C12.2 C13.1 C14.1 C15.1 C16.1 C17.2 C23.1 C24.1 C25.1 C26.1 C27.1 C28.1 C30.2 C32.1 C33.1 C34.2 D1.1 D2.2 D3.1 D4.2 D5.1 D6.2 D9.1 FB2.2 J1.3 J2.3 J4.2 J5.4 J6.3 J7.2 J9.2 J10.2 K1.3 LED1.2 Q3.2 Q6.1 Q9.2 Q10.2 R3.1 R4.1 R5.1 R16.2 R18.2 R22.1 R23.1 R30.1 R31.1 R34.1 R38.2 R39.1 R40.2 R45.2 R48.1 R50.1 S1.9 S1.10 S1.11 S1.12 S1.13 S1.14 S1.15 S1.16 U1.0 U1.5 U2.1 U3.4 U4.5 U5.5 U5.14 U5.15 U6.8 U6.23 U6.35 U6.47 U7.7 U8.7 U14.4 | length 197.6
  Top Layer w0.203: S1.16@1.651,20.519 2.921,20.519 4.191,20.519 5.461,20.519 6.731,20.519 8.001,20.519 9.271,20.519 S1.9@10.541,20.519 ; U5.5 6.528,34.9 6.985,34.442 8.738,34.442 ; C17.2 10.084,42.164 R18.2 C16.1 ; U5.15 U5.14 9.068,34.112 ; C14.1 9.398,34.442 ; v2(15.697,18.567) C25.1 ; LED1.2 C26.1 ; U2.1 18.542,41.593 C12.2 18.542,38.024 19.71,36.855 v1(19.71,36.043) ; v1(22.352,24.638) 22.352,24.714 C27.1 ; J7.2@24.79,1.549 J7.2 ; v1(25.095,4.699) 26.73,4.699 29.296,2.134 J6.3 J6.3@30.886,1.549 ; C5.1@27.851,38.951 28.524,38.278 C2.1 28.524,33.401 C4.1@28.499,33.376 ; C10.2 29.515,21.717 C15.1@29.515,19.38 ; C15.1 C15.1@29.515,19.38 ; v1(30.429,20.295) C15.1@29.515,19.38 ; C7.2@34.265,35.255 C7.2 C3.2@34.468,37.414 ; v1(56.909,13.957) 57.188,13.957 D5.1 ; 8.738,34.442 9.068,34.112 ; 8.738,34.442 9.068,34.442 ; 9.068,34.112 9.068,34.442 ; 9.068,34.112 9.398,34.442 ; 9.068,34.442 9.398,34.442
  Top Layer w0.254: v1(27.864,22.606) 28.626,22.606 C10.2 ; U1.0@38.786,28.321 v1(40.894,28.321)
  Top Layer w0.6: U3.4@11.938,22.581 U3.4 14.224,22.581 14.783,23.139 14.783,26.772 v1(13.691,27.864) ; U1.5 40.615,32.309 42.189,33.884 R4.1 ; R16.2 v1@42.393,5.055 ; R5.1@41.605,22.708 44.933,22.708 45.187,22.962 R3.1 ; D5.1 60.147,13.005 60.833,13.691 FB2.2 ; Q6.1 59.944,7.696 R31.1 59.944,12.802
  Top Layer w1: R3.1 46.796,23.994 C30.2
  Bottom Layer w0.203: v2(15.697,18.567) 16.19,18.074 U6.35 ; J7.2 26.314,3.658 R22.1 v1(25.095,4.699) ; v1(27.864,22.606) 27.864,22.2 28.59,21.474 U6.47 ; U6.8 31.687,15.074 ; R30.1 47.854,5.258 v1(49.124,5.258) ; v1(56.909,13.957) 56.909,15.024 Q10.2
  Bottom Layer w0.254: C13.1 C28.1 ; D3.1 D2.2 ; R30.1 46.634,4.039 43.231,4.039 42.418,4.851 v1(42.418,5.08) v1(42.418,9.906) 42.418,14.656 43.84,16.078 46.482,16.078 R39.1 ; R34.1 48.895,8.636 v1(50.292,8.636) 55.042,8.636 ; Q9.2@56.744,10.033 Q9.2 55.931,9.042 55.448,9.042 55.042,8.636 ; Q3.2@56.744,5.715 Q3.2 55.88,6.756 55.321,6.756 55.042,7.036 55.042,8.636
  Bottom Layer w0.3: U7.7 55.016,27.127 56.032,26.111 v1(56.032,24.663) 56.032,20.777 55.677,20.422 55.677,19.456 R23.1
  Bottom Layer w0.6: v2(64.389,25.146) 65.608,26.365 U8.7 ; C32.1 R38.2 65.024,56.642 66.802,58.42 72.771,58.42 74.295,56.896 R40.2 C33.1
  other v1: 69.088,1.778 71.628,1.778 6.985,1.905 60.706,2.286 73.66,2.54 69.088,4.064 71.628,4.064 6.985,4.445 17.145,5.08 65.024,5.334 13.335,5.715 77.47,6.35 69.088,6.604 28.067,6.731 17.145,7.62 19.685,7.62 7.62,8.89 76.2,8.89 69.088,9.398 71.628,9.398 74.422,9.398 17.145,10.16 19.685,10.16 66.04,10.16 1.27,10.795 30.988,11.303 55.88,11.43 76.2,11.43 12.065,12.7 35.433,13.716 73.66,13.97 76.2,13.97 68.58,15.24 35.306,16.002 71.12,16.51 73.66,16.51 76.2,16.51 10.16,17.145 1.27,17.78 66.04,18.415 12.065,19.05 35.306,19.05 71.12,19.05 73.66,19.05 76.2,19.05 78.105,19.05 67.31,19.685 78.105,21.59 78.105,24.765 59.538,24.943 61.697,24.943 47.371,25.654 78.105,27.305 78.105,29.845 73.025,32.385 75.565,32.385 78.105,32.385 17.526,33.604 44.45,34.29 47.625,34.29 78.105,34.925 28.575,35.56 30.48,37.465 78.105,37.465 16.789,37.795 34.29,39.37 78.105,40.005 78.105,42.545 34.29,43.18 46.99,43.18 48.26,44.45 78.105,45.085 46.355,46.355 34.29,46.99 48.26,47.625 78.105,47.625 78.105,50.165 62.865,50.8 2.54,52.07 78.105,52.705 62.23,53.34 55.88,54.61 65.024,55.245 74.295,55.245 60.325,58.42 64.135,58.42 67.945,58.42 71.755,58.42
  other v2: 38.71,28.397 2.54,33.528 5.08,33.528 7.62,33.528 10.16,33.528 7.62,44.45 7.62,46.99
IIC1_SCL: R6.1 U3.6 U6.42 | length 15.9
  Top Layer w0.203: R6.1@16.129,27.762 16.129,24.638 16.916,23.851 U3.6 23.851,23.851 v1(24.968,22.733)
  Bottom Layer w0.203: v1(24.968,22.733) 26.09,21.611 U6.42
IIC1_SDA: R7.1 U3.5 U6.43 | length 23.1
  Top Layer w0.203: R7.1 14.91,29.261 14.91,27.534 15.697,26.746 15.697,23.851 16.967,22.581 U3.5 23.47,22.581 24.689,21.361 v1(24.689,18.694)
  Bottom Layer w0.203: v1(24.689,18.694) 26.06,18.694 26.59,19.224 U6.43
IN1: U6.15 U12.2 | length 13.3
  Bottom Layer w0.203: U6.15 28.09,10.264 28.448,9.906 36.119,9.906 38.481,12.268 U12.2
IN2: U6.14 U13.2 | length 17.3
  Bottom Layer w0.203: U6.14 28.59,10.526 28.778,10.338 35.738,10.338 36.855,11.455 36.855,16.485 37.668,17.297 U13.2
LED: R19.2 U6.29 | length 4.4
  Top Layer w0.203: R19.2 v1@19.419,15.062
  Bottom Layer w0.203: v1(19.431,15.074) U6.29
LIMIT_SW1: J9.1 R14.1 U6.27 | length 15.7
  Bottom Layer w0.203: R14.1 J9.1 12.167,10.414 13.081,10.414 16.129,13.462 19.685,13.462 20.297,14.074 U6.27
LIMIT_SW2: J10.1 R25.2 U6.28 | length 24
  Bottom Layer w0.203: R25.2 J10.1 4.648,10.922 12.954,10.922 16.002,13.97 19.558,13.97 20.162,14.574 U6.28
M1_1: C32.2 J8.1 Q5.1 Q8.1 R38.1
  other v2: 50.8,42.672 52.324,42.672 53.848,42.672 55.372,42.672 50.8,44.196 52.324,44.196 53.848,44.196 55.372,44.196 50.8,45.72 52.324,45.72 53.848,45.72 55.372,45.72 50.8,47.244 52.324,47.244 53.848,47.244 55.372,47.244 50.8,48.768 52.324,48.768 53.848,48.768 55.372,48.768
M1_2: C33.2 J8.2 Q4.1 Q7.1 R40.1 | length 5
  Bottom Layer w0.6: J8.2 J8.2 R40.1 C33.2
NetC1_1: C1.1 U1.8 | length 3.9
  Top Layer w0.6: C1.1 36.195,32.944 36.805,32.334 U1.8
NetC1_2: C1.2 D1.2 L1.1 U1.1 | length 1
  Top Layer w0.6: L1.1@33.785,24.409 L1.1@33.807,24.432 ; U1.1 U1.1@36.805,26.568
NetC3_1: C3.1 C7.1 F1.2 R1.2 U1.7 | length 25.7
  Top Layer w0.6: v2(35.789,22.911) 35.789,21.869 R1.2 ; U1.7 38.075,33.934 C7.1 39.079,37.581 C3.1 F1.2
  Bottom Layer w0.6: v2(35.789,22.911) 37.465,24.587 37.465,28.946 38.075,29.556 v2(38.075,33.045)
NetC8_2: C8.2 C9.2 C12.1 FB1.1 U2.0 U2.2 | length 16
  Top Layer w0.6: U2.0 U2.2 21.438,39.929 C12.1@21.996,39.37 ; FB1.1 21.996,38.354
NetC11_1: C11.1 U1.3 | length 2.8
  Top Layer w0.203: C11.1@39.345,22.758 U1.3
NetC11_2: C11.2 R5.2 | length 2.2
  Top Layer w0.203: C11.2@39.395,20.422 R5.2@41.605,20.422
NetC18_1: C18.1 R8.1 U5.7 | length 8
  Top Layer w0.203: U5.7 3.988,40.894 C18.1 R8.1
NetC18_2: C18.2 R20.1 U5.8 | length 7.6
  Top Layer w0.203: U5.8 C18.2 R20.1
NetC19_1: C19.1 R9.1 U5.9 | length 7.9
  Top Layer w0.203: R9.1 C19.1 2.718,26.365 U5.9
NetC19_2: C19.2 R21.1 U5.10 | length 7.6
  Top Layer w0.203: C19.2@3.988,25.4 U5.10 ; C19.2 R21.1
NetC21_2: C21.2 FB2.1 U9.1 | length 5.9
  Top Layer w0.6: C21.2 56.109,15.316 56.363,15.062 FB2.1 58.572,15.088 U9.1
NetD5_2: D5.2 Q2.1 R13.2 | length 5.4
  Top Layer w0.6: Q2.1 52.602,12.991 54.319,12.991 54.331,12.979 R13.2@54.331,10.49
NetD8_1: D8.1 R24.2 U7.4 U7.5 U8.2 U8.4 | length 32.3
  Top Layer w0.203: D8.1 v1(60.376,17.831)
  Bottom Layer w0.203: U7.4 U7.5 52.476,29.82 53.264,30.607 58.547,30.607 59.258,29.896 U8.2 59.258,26.619 ; v1(60.376,17.831) 59.842,17.297 R24.2 57.048,18.186 57.048,24.409 59.258,26.619 ; U8.4 61.798,26.619 61.443,26.264 59.614,26.264 59.258,26.619
NetD8_2: D8.2 U9.2 | length 2.8
  Top Layer w0.6: U9.2 58.572,18.745 D8.2
NetD10_1: D10.1 R30.2 U11.3 | length 4.5
  Bottom Layer w0.203: U11.3 R30.2 D10.1
NetD10_2: D10.2 R12.1 R29.1 | length 4.5
  Bottom Layer w0.203: R12.1 48.819,2.464 D10.2 R29.1
NetD11_1: D11.1 Q6.2 R31.2 | length 3.9
  Top Layer w0.6: D11.1@55.855,8.407 Q6.2 R31.2
NetD12_1: D12.1 R34.2 R36.1 U8.1 U12.3 | length 30.9
  Top Layer w0.203: v1(49.53,11.303) 49.53,12.7 49.428,12.802 49.428,24.689 50.317,25.578 57.15,25.578 v1(57.988,26.416)
  Bottom Layer w0.203: U12.3 R34.2 D12.1 R36.1 ; v1(57.988,26.416) U8.1
NetD12_2: D12.2 D13.2 R23.2 R24.1 | length 11.6
  Bottom Layer w0.203: D12.2 53.365,13.462 53.924,14.021 55.626,14.021 55.905,14.3 55.905,17.043 R24.1 D13.2 R23.2
NetD13_1: D13.1 R39.2 R43.1 U8.5 U13.3 | length 38.7
  Bottom Layer w0.203: R43.1 D13.1 R39.2 U13.3 45.314,28.296 48.184,31.166 61.697,31.166 63.068,29.794 U8.5
NetF2_1: F2.1 Q2.2 | length 4.8
  Top Layer w0.6: 45.264,10.491 Q2.2@45.264,15.291
NetJ11_2: J11.2 R10.2 | length 4.2
  Top Layer w0.3: J11.2 27.483,49.759 28.88,48.362 R10.2
NetLED1_1: LED1.1 R19.1 | length 2.2
  Top Layer w0.203: LED1.1@15.418,12.893 R19.1
NetQ1_2: Q1.2 U5.2 | length 12.3
  Top Layer w0.203: U5.2 10.338,38.964 11.151,39.776 14.503,39.776 16.688,41.961 Q1.2
NetQ3_1: Q3.1 R29.2 | length 3.1
  Bottom Layer w0.203: R29.2 Q3.1
NetQ3_3: Q3.3 R26.1 R27.2 | length 4.9
  Bottom Layer w0.203: Q3.3 R27.2 R26.1
NetQ9_1: Q9.1 R36.2 | length 3.2
  Bottom Layer w0.203: R36.2 Q9.1
NetQ9_3: Q9.3 R33.1 R35.2 | length 4.8
  Bottom Layer w0.203: Q9.3 R35.2 R33.1
NetQ10_1: Q10.1 R43.2 | length 3.2
  Bottom Layer w0.203: R43.2 Q10.1
NetQ10_3: Q10.3 R41.1 R42.2 | length 4.9
  Bottom Layer w0.203: Q10.3 R42.2 R41.1
NetR1_1: R1.1 U1.2 | length 3.2
  Top Layer w0.203: R1.1 38.075,23.546 U1.2
NetR2_1: R2.1 R51.2 | length 2
  Top Layer w0.6: R2.1 R51.2
NetR2_2: R2.2 R3.2 U1.4 | length 4.6
  Top Layer w0.6: U1.4 R3.2 R2.2
NetR4_2: R4.2 U1.6 | length 4.3
  Top Layer w0.6: U1.6 39.345,32.944 39.903,33.503 R4.2
NetR11_1: R11.1 U4.2 U4.3 | length 7.4
  Bottom Layer w0.203: U4.3 U4.2 14.249,32.944 14.478,33.172 16.561,33.172 17.221,32.512 R11.1
NetR12_2: R12.2 U7.6 | length 44.1
  Top Layer w0.203: v1(53.746,29.972) v1(53.746,32.106)
  Bottom Layer w0.203: R12.2 43.79,2.464 41.758,4.496 41.758,16.002 44.729,18.974 44.729,28.346 48.489,32.106 v1(53.746,32.106) ; U7.6 v1(53.746,29.972)
NetR17_1: R17.1 R18.1 U5.4 | length 10.4
  Top Layer w0.203: U5.4 7.798,39.345 9.169,40.716 11.176,40.716 R17.1 R18.1
NetR26_2: R26.2 U10.2 U10.4 | length 36.7
  Top Layer w0.203: v1@62.662,7.188 62.662,18.542 72.415,28.296 v1(72.415,30.048)
  Bottom Layer w0.203: R26.2 61.265,5.664 62.382,5.664 62.662,5.944 v1(62.662,6.934) ; U10.2 69.875,26.899 70.079,26.695 72.161,26.695 72.415,26.949 U10.4 v1(72.415,30.048)
NetR28_2: R28.2 U11.1 | length 17.4
  Bottom Layer w0.203: U11.1 39.37,4.699 41.123,6.452 41.123,17.145 43.663,19.685 R28.2
NetR32_2: R32.2 U12.1 | length 11.7
  Bottom Layer w0.203: U12.1 39.421,9.728 40.513,10.82 40.513,17.272 41.885,18.644 R32.2
NetR33_2: R33.2 U10.1 | length 21.6
  Top Layer w0.203: v1(61.239,11.227) 62.103,12.09 62.103,19.075 v1(68.605,25.578)
  Bottom Layer w0.203: R33.2 v1(61.239,11.227) ; v1(68.605,25.578) U10.1
NetR37_2: R37.2 U13.1 | length 6
  Bottom Layer w0.203: U13.1 39.472,14.757 40.107,15.392 R37.2
NetR41_2: R41.2 U10.5 | length 21
  Top Layer w0.203: v1(63.322,14.935) 63.322,18.491 71.653,26.822 v1(73.685,26.822)
  Bottom Layer w0.203: R41.2 v1(63.322,14.935) ; v1(73.685,26.822) U10.5
NetR44_1: R44.1 U6.10 U14.1 | length 26
  Top Layer w0.203: v1(26.797,28.931) 26.797,21.692 28.372,20.117 v1(28.372,16.688)
  Bottom Layer w0.203: v1(26.797,28.931) 26.797,32.207 27.254,32.664 U14.1 R44.1 ; v1(28.372,16.688) 28.372,15.164 29.461,14.074 U6.10
NetR44_2: R44.2 R45.1 U14.2 | length 7.8
  Bottom Layer w0.203: U14.2 33.223,31.394 R44.2 R45.1
NetR46_1: R46.1 U14.3 | length 3.2
  Bottom Layer w0.203: U14.3 R46.1
NetR52_2: R52.2 U5.11 | length 3
  Top Layer w0.203: R52.2 U5.11
NetR53_2: R53.2 U5.12 | length 5.4
  Top Layer w0.203: U5.12 6.528,29.388 7.01,28.905 8.865,28.905 R53.2
NRST: C15.2 R15.1 U6.7 | length 4
  Top Layer w0.203: R15.1 29.286,14.834 v1(29.286,15.824) 29.286,16.815 C15.2
  Bottom Layer w0.203: v1(29.286,15.824) 29.536,15.574 U6.7
OSC1: C23.2 U6.5 Y1.2 | length 7.7
  Top Layer w0.203: Y1.2 35.687,17.45 C23.2
  Bottom Layer w0.203: U6.5 31.814,16.574 32.69,17.45 Y1.2
OSC2: C24.2 U6.6 Y1.1 | length 10.1
  Top Layer w0.203: Y1.1 36.017,12.37 C24.2
  Bottom Layer w0.203: U6.6 32.592,16.074 33.858,14.808 Y1.1
REFER: C22.2 C31.1 D7.1 Q6.3 U10.7 | length 44.3
  Top Layer w0.6: D7.1 54.661,3.962 C31.1 C22.2 54.331,6.299 54.534,6.502 Q6.3 58.217,5.944 63.297,5.944 64.237,6.883 64.237,18.415 71.476,25.654 v2(76.225,25.654)
  Bottom Layer w0.6: 76.225,26.06 U10.7
RS485_A: D3.2 J1.1 J2.1 J11.1 R50.2 U4.6 | length 71.6
  Top Layer w0.3: J2.1 44.615,58.293 54.483,58.293 58.039,54.737 60.401,54.737 J1.1
  Bottom Layer w0.3: U4.6 12.979,41.478 16.002,44.501 22.479,44.501 D3.2@23.805,45.827 ; D3.2@24.663,46.685 D3.2@23.805,45.827 ; J2.1 40.399,58.75 29.007,58.75 26.695,56.439 J11.1 23.012,48.616 R50.2 22.53,47.102 D3.2@23.805,45.827
RS485_B: D2.1 J1.2 J2.2 R10.1 R49.1 U4.7 | length 71.2
  Top Layer w0.3: v1(26.174,43.866) 26.594,44.285 R10.1 ; J2.2 41.567,59.055 55.626,59.055 J1.2
  Bottom Layer w0.3: U4.7 14.249,41.504 16.612,43.866 v1(26.174,43.866) D2.1 ; R49.1@31.027,45.835 D2.1 ; J2.2 38.925,57.518 38.354,58.09 29.667,58.09 28.143,56.566 D2.1
SENSOR: Q7.3 Q8.3 R46.2 R48.2 | length 27.5
  Top Layer w0.203: Q7.3@65.507,34.375 Q7.3
  Top Layer w4: 60.706,39.37 v2(62.431,37.645) v2(63.512,36.564) v2(64.516,35.56) 65.024,35.052
  Bottom Layer w0.203: R46.2 35.814,31.445 35.814,34.747 36.525,35.458 41.681,35.458 42.924,36.701 R48.2
  Bottom Layer w4: v2@61.485,38.591 61.468,38.608 v2@61.366,38.608 ; v2@63.246,36.83 v2(63.512,36.564) ; v2@63.754,36.322 64.008,36.068 ; v2@64.262,35.814 64.008,36.068 ; v2@61.366,38.608 61.341,38.608 60.96,38.989 v2@61.366,38.608 ; v2@61.366,38.608 61.424,38.553 61.721,38.275 62.413,37.624 62.753,37.305 63.029,37.045 63.055,37.02 v2(63.512,36.564) ; v2(63.512,36.564) 64.008,36.068
  other v2: 63.5,34.925 62.23,36.195 64.77,36.83 60.96,37.465 63.5,38.1 61.595,38.735 61.595,40.005
SENSOR_A+: J4.4 R20.2 | length 19
  Top Layer w0.203: R20.2 9.55,53.442 15.316,53.442 16.468,54.593 J4.4
SENSOR_A-: J4.3 R8.2 | length 20
  Top Layer w0.203: R8.2 5.004,48.082 9.754,52.832 17.094,52.832 19.008,54.746 J4.3
SENSOR_B+: R21.2
SENSOR_B-: R9.2
SENSOR_DOUT: R53.1 U6.18 | length 27.2
  Top Layer w0.203: R53.1 9.906,23.47 10.232,23.143 12.09,21.285 22.784,21.285 24.058,20.011 24.058,18.411 25.476,16.993 v1(25.476,14.275)
  Bottom Layer w0.203: v1(25.476,14.275) 25.476,13.818 26.59,12.704 U6.18
SENSOR_E+: C16.2 J4.1 Q1.1 R17.2 U5.3 | length 34.4
  Top Layer w0.203: U5.3 9.068,39.141 10.185,40.259 13.005,40.259 R17.2 Q1.1 13.843,46.228 C16.2 12.37,49.225 15.24,52.095 22.022,52.095 24.088,54.161 J4.1
SENSOR_SCK: R52.1 U6.19 | length 30.2
  Top Layer w0.203: R52.1 7.544,25.222 12.04,20.726 22.581,20.726 23.495,19.812 23.495,18.39 24.867,17.018 v1(24.867,13.462)
  Bottom Layer w0.203: v1(24.867,13.462) 25.197,13.462 26.09,12.569 U6.19
SW1: S1.1 U6.46 | length 35.4
  Top Layer w0.203: S1.1@1.651,12.399 S1.1 v1(1.651,13.741)
  Bottom Layer w0.203: v1(1.651,13.741) 1.651,15.669 2.159,16.177 9.812,23.83 25.598,23.83 28.09,21.339 U6.46
SW2: S1.2 U6.45 | length 33.4
  Top Layer w0.203: S1.2@2.921,12.399 S1.2 v1(2.921,13.741)
  Bottom Layer w0.203: v1(2.921,13.741) 2.921,16.202 3.429,16.71 10.07,23.351 25.367,23.351 27.59,21.127 U6.45
SW3: S1.3 U6.41 | length 30.1
  Top Layer w0.203: S1.3@4.191,12.399 v1(4.191,13.741)
  Bottom Layer w0.203: v1(4.191,13.741) 4.191,16.726 10.325,22.86 23.901,22.86 25.59,21.172 U6.41
SW4: S1.4 U6.40 | length 28.2
  Top Layer w0.203: S1.4@5.461,12.399 v1(5.461,13.741)
  Bottom Layer w0.203: v1(5.461,13.741) 5.461,17.289 10.6,22.428 23.749,22.428 25.09,21.087 U6.40
SW5: S1.5 U6.39 | length 26.4
  Top Layer w0.203: S1.5@6.731,12.399 v1(6.731,13.741)
  Bottom Layer w0.203: v1(6.731,13.741) 6.731,17.852 10.875,21.996 23.597,21.996 24.59,21.003 U6.39
SW6: S1.6 U6.38 | length 24.5
  Top Layer w0.203: S1.6@8.001,12.399 v1(8.001,13.741)
  Bottom Layer w0.203: v1(8.001,13.741) 8.001,18.415 11.151,21.565 23.431,21.565 24.09,20.906 U6.38
SW7: S1.7 U6.33 | length 15.5
  Top Layer w0.203: S1.7@9.271,12.399 v1(9.271,13.741)
  Bottom Layer w0.203: v1(9.271,13.741) 10.897,15.367 14.199,15.367 15.906,17.074 U6.33
SW8: S1.8 U6.32 | length 14.1
  Top Layer w0.203: S1.8@10.541,12.399 v1(10.541,13.741)
  Bottom Layer w0.203: v1(10.541,13.741) 11.659,14.859 14.3,14.859 16.015,16.574 U6.32
SWCLK: J5.3 U6.37 | length 29.4
  Top Layer w0.203: J5.3 15.24,5.74 15.24,9.779 13.437,11.582 13.437,18.517 14.783,19.863 v1(22.022,19.863)
  Bottom Layer w0.203: v1(22.022,19.863) 22.606,19.863 22.817,20.074 U6.37
SWDIO: J5.2 U6.34 | length 24.7
  Top Layer w0.203: J5.2@14.173,1.549 J5.2 15.748,3.708 15.748,9.906 14.173,11.481 v1(14.173,16.612)
  Bottom Layer w0.203: v1(14.173,16.612) 15.136,17.574 U6.34
SWITCH_21: Q5.2 U10.3 | length 23
  Top Layer w0.203: Q5.2 62.518,41.427 66.827,41.427 68.047,40.208 68.047,33.35 v1(71.145,30.251)
  Bottom Layer w0.203: U10.3 v1(71.145,30.251)
SWITCH_22: Q8.2 U8.3 | length 7.2
  Top Layer w0.203: Q8.2 59.815,30.711 v1(60.528,29.997)
  Bottom Layer w0.203: U8.3 v1(60.528,29.997)
SWITCH_23: Q4.2 U10.6 | length 25.9
  Top Layer w0.203: Q4.2 68.504,46.448 68.504,33.909 71.704,30.709 v1(74.955,30.709)
  Bottom Layer w0.203: U10.6 v1(74.955,30.709)
SWITCH_24: Q7.2 U8.6 | length 13.1
  Top Layer w0.203: v1@66.195,38.077 Q7.2
  Bottom Layer w0.203: U8.6 64.338,29.997 67.183,32.842 67.183,37.084 v1(66.192,38.075)
UART1_RX: J6.1 U6.31 | length 24
  Top Layer w0.203: v1(23.419,16.332) 24.232,15.519 24.232,8.407 28.829,3.81 34.29,3.81 J6.1
  Bottom Layer w0.203: U6.31 23.161,16.074 v1(23.419,16.332)
UART1_TX: J6.2 U6.30 | length 20.8
  Top Layer w0.203: v1(23.571,15.164) 23.571,8.433 28.702,3.302 32.258,3.302 J6.2
  Bottom Layer w0.203: U6.30 23.161,15.574 v1(23.571,15.164)
VBG: C17.1 U5.6 | length 6.1
  Top Layer w0.203: U5.6 5.258,38.252 7.544,40.538 C17.1
VDD: C21.1 C30.1 D9.2 Q2.3 U7.14 U8.14 U9.3 U11.4 U12.4 U13.4 | length 45.7
  Top Layer w0.6: v2(50.216,13.716) 50.216,16.043 51.764,17.591 ; C30.1@51.764,20.607 51.764,17.591 ; D9.2 57.429,23.393 v1(57.988,23.952) ; U9.3@56.529,17.591 51.764,17.591
  Bottom Layer w0.4: U11.4 44.094,4.699 43.739,5.055 43.739,9.195 44.272,9.728 ; U12.4 44.272,9.728 ; v2(50.216,13.716) 46.787,13.716 45.745,14.757 44.196,14.757 43.764,14.326 43.764,10.236 44.272,9.728
  Bottom Layer w0.6: U7.14 47.396,24.028 48.133,24.765 50.241,24.765 v2(50.952,24.054) ; U8.14 v1(57.988,23.952)
pads on no net: K1.2 K1.4 U3.1 U3.2 U3.3 U3.7 U5.13 U6.2 U6.3 U6.4 U6.25 U6.26 U7.1 U7.2 U7.3 U7.8 U7.9 U7.10 U7.11 U7.12 U7.13 U8.8 U8.9 U8.10 U8.11 U8.12 U8.13 U10.8 U10.9 U10.10 U10.11 U10.12 U10.13 U14.5 U14.6 U14.7

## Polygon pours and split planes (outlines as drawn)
GND on Top Layer "Top Layer-No Net" (solid, remove dead copper, pour order 1000): 0,60 0,0 80,0 80,60
GND on Bottom Layer "Top Layer-No Net" (solid, remove dead copper, pour order 1001): 0,60 0,0 80,0 80,60

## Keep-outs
Keep-Out Layer:
  circle w0.127: c77,57 r1.5
  circle w0.127: c77,3 r1.5
  circle w0.127: c3,3 r1.5
  circle w0.127: c3,57 r1.5
  lines w0.127: 0,0 80,0 80,60 0,60 0,0

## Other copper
Top Layer:
  rectangle net +24V: 39.116,43.688 43.815,54.102
  rectangle net +24V: 29.464,50.292 52.832,54.864
  rectangle net +24V: 48.26,52.451 52.832,57.658
  rectangle net VDD: 50.521,16.866 52.959,24.486
  rectangle net GND: 44.425,19.228 48.006,26.264
  rectangle net M1_2: 69.113,34.112 76.276,49.708
  rectangle net M1_1: 49.682,34.188 56.896,49.657
  rectangle net NetC1_2: 33.376,24.333 37.084,26.848
  rectangle net GND: 33.02,37.465 37.084,47.752
  rectangle net GND: 26.645,34.595 35.23,39.091
  rectangle net GND: 27.737,31.801 29.286,38.176
  region net +24V: 30.988,58.293 29.464,56.769 29.464,52.832 32.131,50.292 46.101,50.292 46.609,53.467 43.053,54.356 34.671,54.356 33.655,55.372 33.655,57.277 32.639,58.293
  region net M1_2: 70.764,56.49 70.764,53.137 69.113,51.486 69.113,47.777 76.276,47.777 76.276,51.511 73.254,54.534 73.254,56.49 72.619,57.125 71.577,57.125
  region net NetC1_2: 35.306,23.647 33.325,23.647 33.325,27.559 30.81,30.074 30.81,31.445 34.925,31.445 35.306,31.064
  pour cut-out: 27.305,28.677 27.305,23.673 27.33,23.647 35.306,23.647 35.306,28.677
Bottom Layer:
  rectangle net SENSOR: 42.164,35.814 62.611,40.005
  rectangle net GND: 33.782,50.292 56.642,54.737
  rectangle net GND: 52.197,50.165 56.642,59.055
  rectangle net GND: 32.893,36.195 37.465,57.658
  region net M1_1: 67.285,56.921 66.472,56.109 66.472,49.784 66.065,49.479 63.957,49.505 49.733,49.505 49.733,42.113 49.708,42.088 49.759,42.037 63.576,42.037 69.367,47.828 69.367,56.134 68.58,56.921

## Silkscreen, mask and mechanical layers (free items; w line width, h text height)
Top Overlay:
  text "A+" at 14.986,52.553 h1
  text "A-" at 17.678,52.553 h1
  text "E-" at 20.396,52.553 h1
  text "E+" at 23.012,52.553 h1
  text "+24V" at 48.26,51.435 h1
  text "GND" at 52.959,51.435 h1
  text "485B" at 56.134,51.435 h1
  text "485A" at 60.198,51.435 h1
  text "GND" at 33.731,51.232 h1
  text "+24V" at 29.21,51.181 h1
  text "485B" at 36.957,51.181 h1
  text "485A" at 41.148,51.181 h1
  text "YarnControl_Driver_v1.3" at 53.061,27.864 h1
  text "2018.12.21" at 60.579,26.289 h1
  text "RX" at 19.05,4.064 h1
  text "TX" at 21.463,4.064 h1
  text "GND" at 23.622,4.064 h1
  text "3.3" at 26.67,4.064 h1
  text "GND" at 29.845,4.064 h1
  text "TX" at 32.893,4.064 h1
  text "RX" at 35.179,4.064 h1
  text "GND" at 7.366,0.127 h1
  text "CLK" at 10.414,0.127 h1
  text "IO" at 13.462,0.127 h1
  text "3.3" at 15.494,0.127 h1
Top Solder:
  lines w3: 59.815,39.638 60.565,39.638 65.14,35.063 66.195,35.063 ; 59.815,50.802 59.815,48.796 64.454,44.157 66.195,44.157

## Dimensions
0,0 to 0,60 on Top Overlay
0,0 to 80,0 on Top Overlay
